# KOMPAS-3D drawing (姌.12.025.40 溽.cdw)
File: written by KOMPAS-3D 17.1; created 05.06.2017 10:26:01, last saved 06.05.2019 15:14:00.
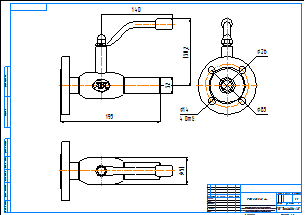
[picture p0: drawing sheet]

Sheet 1: A2, landscape

Title block, sheet 1: name: КШ.12.025.40 фс; material: Внимание! Данный продукт является объектом авторского права ООО «Торговый Дом АДЛ». / Запрещается изменение, копирование, распространение / (в том числе путем копирования на другие сайты и ресурсы в Интернете) / или любое иное использование информации и объектов без предварительного / согласия правообладателя (ООО «Торговый Дом АДЛ»).; sheets: 1; organisation: ООО "Торговый дом АДЛ"; sheet format: A2; stored path: C:\Users\kka\KOMPAS_Work\Модели кранов для исследований\Все краники\Редуцированный резьба-сварка ШК БИВАЛ\КШ.02.015.40 рс.cdw

Views: Вид 1, Проекционный вид 2, Проекционный вид 3
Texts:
  Klimkovich
  ADL
Dimensions and other numbers on the sheet: 130,2; 195; 32; 140; 85; 26; 14; 4 Отв.; 51; 1:1; 1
